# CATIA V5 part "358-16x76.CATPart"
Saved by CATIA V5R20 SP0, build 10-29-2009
Part number: 358-16x76
Definition: NONE
Nomenclature: 358-16x76
Source: Unknown
Description: 358-16x76
Bounding box of the stored display mesh (mm): x -15 to 61, y -13 to 13, z -13 to 13
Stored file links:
  C:\Users\Utente\Desktop\IO LAVORO\3D X SITO CF\X SITO\PLASTICA\358\358-16x76.CATPart
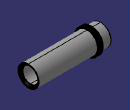
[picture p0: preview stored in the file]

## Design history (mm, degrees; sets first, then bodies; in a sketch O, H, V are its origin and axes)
Body1 "358-16x76" (main body)
  Solid1 "358-16X76": solid without history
